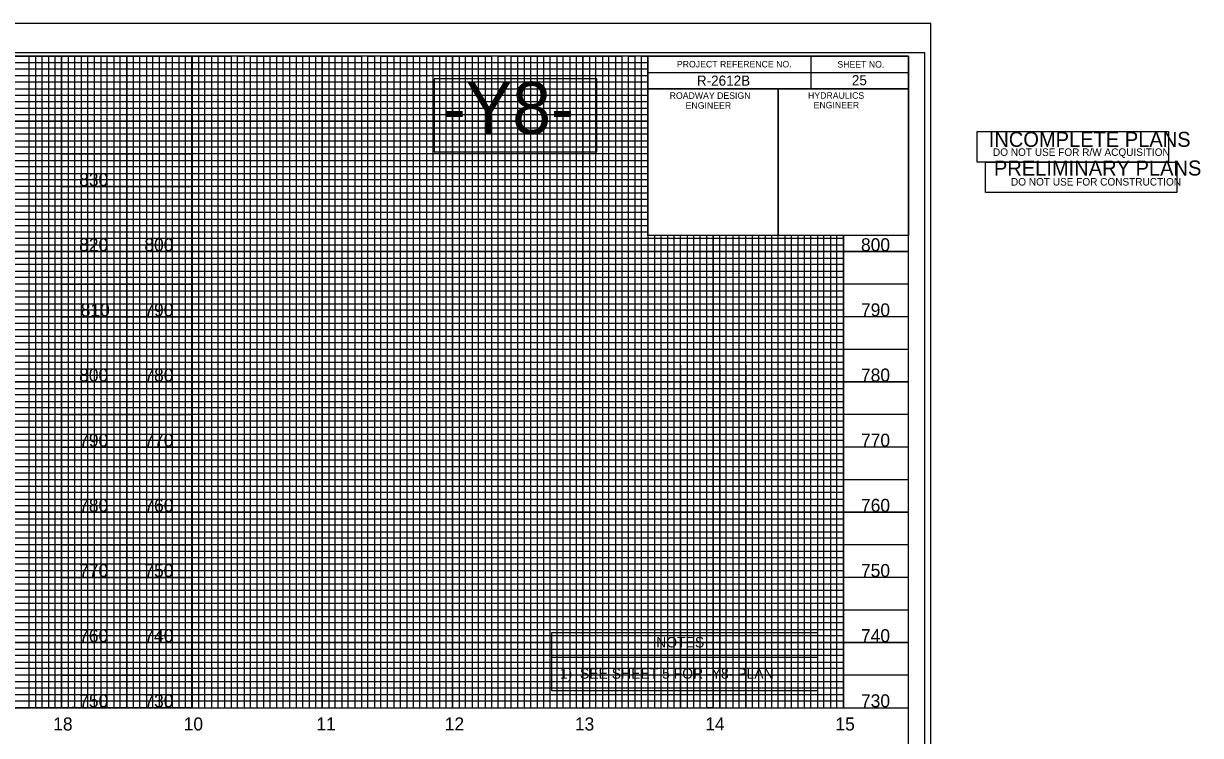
# Model space of a CAD drawing. Extents: x 600491 to 602382, y -54561 to -53461.
# Drawn here: x 601479 to 602382, y -54007 to -53461 of the extents above; entities that cross this region are included whole.
import ezdxf

# ---------------------------------------------------------------- set-up
doc = ezdxf.new("R2010")
doc.units = 0
for name, color, linetype in [('Default', 7, 'Continuous'), ('Exist Vertical Profile Horizontal Axis Label Major', 7, 'Continuous'), ('Exist Vertical Profile Vertical Axis Label', 7, 'Continuous'), ('Prop DSN Text', 7, 'Continuous'), ('Prop Grid Mask', 7, 'Continuous'), ('Prop VPI Label', 7, 'Continuous'), ('Sheet Cutting Line CELL', 7, 'Continuous'), ('Sheet Data Field CELL', 7, 'Continuous'), ('Sheet DOT Grid CELL', 7, 'Continuous'), ('Sheet Layout Profile Border Port 1', 7, 'Continuous'), ('Sheet Plot Border Inside CELL', 7, 'Continuous'), ('Sheet Plot Border Outside CELL', 7, 'Continuous'), ('Sheet Profile CELL', 7, 'Continuous'), ('Sheet Profile Grid Major CELL', 7, 'Continuous'), ('Sheet Profile Grid Middle CELL', 7, 'Continuous'), ('Sheet Profile Grid Minor CELL', 7, 'Continuous'), ('Sheet Sticker Incomplete CELL', 7, 'Continuous'), ('Sheet Sticker Preliminary CELL', 7, 'Continuous')]:
    doc.layers.add(name, color=color, linetype=linetype)

msp = doc.modelspace()

# ---------------------------------------------------------------- linework, layer by layer
at = {"layer": 'Default'}
for points in [[(600708.27, -53985.99), (601508.27, -53985.99), (601508.27, -53485.99), (600708.27, -53485.99)], [(601608.32, -53985.99), (602158.27, -53985.99), (602158.27, -53623.54), (601958.22, -53623.54), (601958.22, -53485.99), (601608.32, -53485.99)]]:
    msp.add_lwpolyline(points, close=True, dxfattribs=at)
at = {"layer": 'Prop Grid Mask'}
for p, q in [((601508.27, -53510.99), (601558.27, -53510.99)), ((601558.32, -53510.99), (601608.32, -53510.99)), ((601508.27, -53535.99), (601558.27, -53535.99)), ((601558.32, -53535.99), (601608.32, -53535.99)), ((601508.27, -53560.99), (601558.27, -53560.99)), ((601558.32, -53560.99), (601608.32, -53560.99)), ((601508.27, -53585.99), (601558.27, -53585.99)), ((601558.32, -53585.99), (601608.32, -53585.99)), ((601508.27, -53610.99), (601558.27, -53610.99)), ((601558.32, -53610.99), (601608.32, -53610.99)), ((601508.27, -53635.99), (601558.27, -53635.99)), ((601558.32, -53635.99), (601608.32, -53635.99)), ((601508.27, -53660.99), (601558.27, -53660.99)), ((601558.32, -53660.99), (601608.32, -53660.99)), ((601508.27, -53685.99), (601558.27, -53685.99)), ((601558.32, -53685.99), (601608.32, -53685.99)), ((601508.27, -53710.99), (601558.27, -53710.99)), ((601558.32, -53710.99), (601608.32, -53710.99)), ((601508.27, -53735.99), (601558.27, -53735.99)), ((601558.32, -53735.99), (601608.32, -53735.99)), ((601508.27, -53760.99), (601558.27, -53760.99)), ((601558.32, -53760.99), (601608.32, -53760.99)), ((601508.27, -53785.99), (601558.27, -53785.99)), ((601558.32, -53785.99), (601608.32, -53785.99)), ((601508.27, -53810.99), (601558.27, -53810.99)), ((601558.32, -53810.99), (601608.32, -53810.99)), ((601508.27, -53835.99), (601558.27, -53835.99)), ((601558.32, -53835.99), (601608.32, -53835.99)), ((601508.27, -53860.99), (601558.27, -53860.99)), ((601558.32, -53860.99), (601608.32, -53860.99)), ((601508.27, -53885.99), (601558.27, -53885.99)), ((601558.32, -53885.99), (601608.32, -53885.99)), ((601508.27, -53910.99), (601558.27, -53910.99)), ((601558.32, -53910.99), (601608.32, -53910.99)), ((601508.27, -53935.99), (601558.27, -53935.99)), ((601558.32, -53935.99), (601608.32, -53935.99)), ((601508.27, -53960.99), (601558.27, -53960.99)), ((601558.32, -53960.99), (601608.32, -53960.99))]:
    msp.add_line(p, q, dxfattribs=at)
for points in [[(601508.27, -53485.99), (601558.27, -53485.99), (601558.27, -53985.99), (601508.27, -53985.99)], [(601558.32, -53485.99), (601608.32, -53485.99), (601608.32, -53985.99), (601558.32, -53985.99)], [(601794.28, -53559.49), (601919.07, -53559.49), (601919.07, -53503.44), (601794.28, -53503.44)], [(601884.12, -53972.85), (602088.47, -53972.85), (602088.47, -53928.56), (601884.12, -53928.56)], [(601884.12, -53947.28), (602088.47, -53947.28), (602088.47, -53928.56), (601884.12, -53928.56)]]:
    msp.add_lwpolyline(points, close=True, dxfattribs=at)
at = {"layer": 'Sheet Cutting Line CELL'}
msp.add_line((602175.27, -53460.99), (600491.27, -53460.99), dxfattribs=at)
at = {"layer": 'Sheet DOT Grid CELL'}
for p, q in [((601508.27, -53985.99), (601508.27, -53485.99)), ((601558.27, -53985.99), (601558.27, -53485.99)), ((601608.27, -53985.99), (601608.27, -53485.99)), ((601658.27, -53985.99), (601658.27, -53485.99)), ((601708.27, -53985.99), (601708.27, -53485.99)), ((601758.27, -53985.99), (601758.27, -53485.99)), ((601808.27, -53985.99), (601808.27, -53485.99)), ((601858.27, -53985.99), (601858.27, -53485.99)), ((601908.27, -53985.99), (601908.27, -53485.99)), ((601958.22, -53535.99), (600658.27, -53535.99)), ((601958.22, -53585.99), (600658.27, -53585.99)), ((601958.27, -53985.99), (601958.27, -53623.54)), ((602008.27, -53985.99), (602008.27, -53623.54)), ((602058.27, -53985.99), (602058.27, -53623.54)), ((602108.27, -53985.99), (602108.27, -53623.54)), ((602158.27, -53635.99), (600658.27, -53635.99)), ((602158.27, -53685.99), (600658.27, -53685.99)), ((602158.27, -53735.99), (600658.27, -53735.99)), ((602158.27, -53785.99), (600658.27, -53785.99)), ((602158.27, -53835.99), (600658.27, -53835.99)), ((602158.27, -53885.99), (600658.27, -53885.99)), ((602158.27, -53935.99), (600658.27, -53935.99))]:
    msp.add_line(p, q, dxfattribs=at)
at = {"layer": 'Sheet Layout Profile Border Port 1'}
for points in [[(601508.27, -53985.99), (600708.27, -53985.99), (600708.27, -53485.99), (601508.27, -53485.99)], [(601608.27, -53485.99), (601608.27, -53985.99), (602108.27, -53985.99), (602108.27, -53623.54), (601958.22, -53623.54), (601958.22, -53485.99)]]:
    msp.add_lwpolyline(points, close=True, dxfattribs=at)
at = {"layer": 'Sheet Plot Border Inside CELL'}
msp.add_lwpolyline([(600504.27, -54538.54), (602170.77, -54538.54), (602170.77, -53483.44), (600504.27, -53483.44)], close=True, dxfattribs=at)
at = {"layer": 'Sheet Plot Border Outside CELL'}
msp.add_lwpolyline([(600491.27, -54560.99), (602175.27, -54560.99), (602175.27, -53460.99), (600491.27, -53460.99)], close=True, dxfattribs=at)
at = {"layer": 'Sheet Profile CELL'}
for p, q in [((602083.27, -53486.04), (602083.27, -53511.04)), ((601958.22, -53498.54), (602158.27, -53498.54)), ((602058.27, -53511.04), (602058.27, -53623.49)), ((600658.27, -53985.99), (602158.27, -53985.99))]:
    msp.add_line(p, q, dxfattribs=at)
for points in [[(602158.27, -53485.99), (600658.27, -53485.99), (600658.27, -54535.99), (602158.27, -54535.99)], [(601958.22, -53485.99), (602158.27, -53485.99), (602158.27, -53511.04), (601958.22, -53511.04)], [(601958.22, -53511.04), (602058.27, -53511.04), (602058.27, -53623.54), (601958.22, -53623.54)], [(602058.27, -53511.04), (602158.27, -53511.04), (602158.27, -53623.54), (602058.27, -53623.54)]]:
    msp.add_lwpolyline(points, close=True, dxfattribs=at)
at = {"layer": 'Sheet Profile Grid Major CELL'}
for points in [[(601458.27, -53485.99), (601508.27, -53485.99), (601508.27, -53985.99), (601558.27, -53985.99), (601558.27, -53485.99), (601608.27, -53485.99), (601608.27, -53985.99), (601658.27, -53985.99), (601658.27, -53485.99), (601708.27, -53485.99), (601708.27, -53985.99), (601758.27, -53985.99), (601758.27, -53485.99), (601808.27, -53485.99), (601808.27, -53985.99), (601858.27, -53985.99), (601858.27, -53485.99), (601908.27, -53485.99), (601908.27, -53985.99), (601958.27, -53985.99), (601958.27, -53485.99), (601984.57, -53485.99)], [(600658.27, -53535.99), (601958.27, -53535.99)], [(601958.27, -53585.99), (600658.27, -53585.99), (600658.27, -53635.99), (602158.27, -53635.99)], [(602008.27, -53623.54), (602008.27, -53985.99), (602058.27, -53985.99), (602058.27, -53985.99), (602058.27, -53623.54)], [(602108.27, -53623.54), (602108.27, -53985.99), (602158.27, -53985.99), (602158.27, -53635.99)], [(602158.27, -53685.99), (600658.27, -53685.99), (600658.27, -53735.99), (602158.27, -53735.99)], [(602158.27, -53785.99), (600658.27, -53785.99), (600658.27, -53835.99), (602158.27, -53835.99)], [(602158.27, -53885.99), (600658.27, -53885.99), (600658.27, -53885.99), (600658.27, -53935.99), (602158.27, -53935.99)]]:
    msp.add_lwpolyline(points, dxfattribs=at)
at = {"layer": 'Sheet Profile Grid Middle CELL'}
msp.add_line((600658.27, -53510.99), (601958.22, -53510.99), dxfattribs=at)
for points in [[(601433.27, -53985.99), (601483.27, -53985.99), (601483.27, -53485.99), (601533.27, -53485.99), (601533.27, -53985.99), (601583.27, -53985.99), (601583.27, -53485.99), (601633.27, -53485.99), (601633.27, -53985.99), (601683.27, -53985.99), (601683.27, -53485.99), (601733.27, -53485.99), (601733.27, -53985.99), (601783.27, -53985.99), (601783.27, -53485.99), (601833.27, -53485.99), (601833.27, -53985.99), (601883.27, -53985.99), (601883.27, -53485.99), (601933.27, -53485.99), (601933.27, -53985.99), (601983.27, -53985.99), (601983.27, -53623.54)], [(601958.27, -53560.99), (600658.27, -53560.99), (600658.27, -53610.99), (601958.27, -53610.99)], [(601983.27, -53723.19), (601983.27, -53985.99), (602033.27, -53985.99), (602033.27, -53623.54)], [(602033.27, -53723.19), (602033.27, -53985.99), (602083.27, -53985.99), (602083.27, -53623.54)], [(602158.27, -53660.99), (600658.27, -53660.99), (600658.27, -53710.99), (601983.27, -53710.99)], [(601983.27, -53710.99), (602158.27, -53710.99)], [(602158.27, -53760.99), (600658.27, -53760.99), (600658.27, -53810.99), (602158.27, -53810.99)], [(602158.27, -53860.99), (600658.27, -53860.99), (600658.27, -53910.99), (602158.27, -53910.99)], [(602158.27, -53960.99), (600658.27, -53960.99)]]:
    msp.add_lwpolyline(points, dxfattribs=at)
at = {"layer": 'Sheet Profile Grid Minor CELL'}
for p, q in [((600708.27, -53490.99), (601958.27, -53490.99)), ((601958.27, -53495.99), (600708.27, -53496.34)), ((600708.27, -53500.99), (601958.27, -53500.99)), ((601958.22, -53620.99), (600708.27, -53620.99)), ((602108.27, -53625.99), (600708.27, -53625.99)), ((602108.27, -53630.99), (600708.27, -53630.99)), ((600708.27, -53640.99), (602108.27, -53640.99)), ((602108.27, -53645.99), (600708.27, -53645.99)), ((600708.27, -53650.99), (602108.27, -53650.99)), ((602108.27, -53670.99), (600708.27, -53670.99)), ((600708.27, -53675.99), (602108.27, -53675.99)), ((602108.27, -53695.99), (600708.27, -53695.99)), ((600708.27, -53700.99), (602108.27, -53700.99)), ((602108.27, -53720.99), (600708.27, -53720.99)), ((600708.27, -53725.99), (602108.27, -53725.99)), ((602108.27, -53730.99), (600708.27, -53730.99)), ((600708.27, -53740.99), (602108.27, -53740.99)), ((602108.27, -53745.99), (600708.27, -53745.99)), ((600708.27, -53750.99), (602108.27, -53750.99)), ((602108.27, -53755.99), (600708.27, -53755.99)), ((600708.27, -53765.99), (602108.27, -53765.99)), ((602108.27, -53770.99), (600708.27, -53770.99)), ((600708.27, -53775.99), (602108.27, -53775.99)), ((602108.27, -53780.99), (600708.27, -53780.99)), ((600708.27, -53790.99), (602108.27, -53790.99)), ((602108.27, -53795.99), (600708.27, -53795.99)), ((600708.27, -53800.99), (602108.27, -53800.99)), ((602108.27, -53805.99), (600708.27, -53805.99)), ((600708.27, -53815.99), (602108.27, -53815.99)), ((602108.27, -53820.99), (600708.27, -53820.99)), ((600708.27, -53825.99), (602108.27, -53825.99)), ((602108.27, -53830.99), (600708.27, -53830.99)), ((600708.27, -53840.99), (602108.27, -53840.99)), ((602108.27, -53845.99), (600708.27, -53845.99)), ((600708.27, -53850.99), (602108.27, -53850.99)), ((602108.27, -53855.99), (600708.27, -53855.99)), ((600708.27, -53865.99), (602108.27, -53865.99)), ((602108.27, -53870.99), (600708.27, -53870.99)), ((602108.27, -53875.99), (600708.27, -53875.99)), ((602108.27, -53880.99), (600708.27, -53880.99)), ((600708.27, -53890.99), (602108.27, -53890.99)), ((602108.27, -53895.99), (600708.27, -53895.99)), ((600708.27, -53900.99), (602108.27, -53900.99)), ((602108.27, -53905.99), (600708.27, -53905.99)), ((600708.27, -53915.99), (602108.27, -53915.99)), ((602108.27, -53920.99), (600708.27, -53920.99)), ((600708.27, -53925.99), (602108.27, -53925.99)), ((602108.27, -53930.99), (600708.27, -53930.99)), ((600708.27, -53940.99), (602108.27, -53940.99)), ((602108.27, -53945.99), (600708.27, -53945.99)), ((600708.27, -53950.99), (602108.27, -53950.99)), ((602108.27, -53955.99), (600708.27, -53955.99)), ((600708.27, -53965.99), (602108.27, -53965.99)), ((602108.27, -53970.99), (600708.27, -53970.99)), ((600708.27, -53975.99), (602108.27, -53975.99))]:
    msp.add_line(p, q, dxfattribs=at)
for points in [[(601478.27, -53485.99), (601488.27, -53485.99), (601488.27, -53985.99), (601493.27, -53985.99), (601493.27, -53485.99), (601498.27, -53485.99), (601498.27, -53985.99), (601503.27, -53985.99), (601503.27, -53485.99), (601513.27, -53485.99), (601513.27, -53985.99), (601517.97, -53985.44), (601518.27, -53985.99), (601518.27, -53485.99), (601523.27, -53485.99), (601523.27, -53985.99), (601528.27, -53985.99), (601528.27, -53485.99), (601538.27, -53485.99), (601538.27, -53985.99), (601543.27, -53985.99)], [(601543.27, -53985.99), (601543.27, -53485.99), (601548.27, -53485.99), (601548.27, -53985.99), (601553.27, -53985.99), (601553.27, -53485.99), (601563.27, -53485.99), (601563.27, -53985.99), (601568.27, -53985.99), (601568.27, -53485.99), (601573.27, -53485.99), (601573.27, -53985.99), (601578.27, -53985.99), (601578.27, -53485.99), (601588.27, -53485.99), (601588.27, -53985.99), (601593.27, -53985.99), (601593.27, -53485.99), (601598.27, -53485.99), (601598.27, -53985.99), (601603.27, -53985.99), (601603.27, -53485.99), (601613.27, -53485.99), (601613.27, -53985.99), (601618.27, -53985.99), (601618.27, -53485.99), (601623.27, -53485.99), (601623.27, -53985.99), (601628.27, -53985.99), (601628.27, -53485.99), (601638.27, -53485.99), (601638.27, -53985.99), (601643.27, -53985.99), (601643.27, -53485.99), (601648.27, -53485.99), (601648.27, -53985.99), (601653.27, -53985.99), (601653.27, -53485.99), (601663.27, -53485.99), (601663.27, -53985.99), (601668.27, -53985.99), (601668.27, -53485.99), (601673.27, -53485.99), (601673.27, -53985.99), (601678.27, -53985.99), (601678.27, -53485.99), (601688.27, -53485.99), (601688.27, -53985.99), (601693.27, -53985.99), (601693.27, -53485.99), (601698.27, -53485.99), (601698.27, -53985.99), (601703.27, -53985.99), (601703.27, -53485.99), (601713.27, -53485.99), (601713.27, -53985.99), (601718.27, -53985.99), (601718.27, -53485.99), (601723.27, -53485.99), (601723.27, -53985.99), (601728.27, -53985.99), (601728.27, -53485.99), (601738.27, -53485.99), (601738.27, -53985.99), (601743.27, -53985.99), (601743.27, -53485.99), (601748.27, -53485.99), (601748.27, -53985.99), (601753.27, -53985.99), (601753.27, -53485.99), (601763.27, -53485.99), (601763.27, -53985.99), (601768.27, -53985.99), (601768.27, -53485.99), (601773.27, -53485.99), (601773.27, -53985.99), (601778.27, -53985.99), (601778.27, -53485.99), (601788.27, -53485.99), (601788.27, -53985.99), (601793.27, -53985.99), (601793.27, -53485.99), (601798.27, -53485.99), (601798.27, -53985.99), (601803.27, -53985.99), (601803.27, -53485.99), (601813.27, -53485.99), (601813.27, -53985.99), (601818.27, -53985.99), (601818.27, -53485.99), (601823.27, -53485.99), (601823.27, -53985.99), (601828.27, -53985.99), (601828.27, -53485.99), (601838.27, -53485.99), (601838.27, -53985.99), (601843.27, -53985.99), (601843.27, -53485.99), (601848.27, -53485.99), (601848.27, -53985.99)], [(601848.27, -53985.99), (601853.27, -53985.99), (601853.27, -53485.99), (601863.27, -53485.99), (601863.27, -53985.99), (601868.27, -53985.99), (601868.27, -53485.99), (601873.27, -53485.99), (601873.27, -53985.99), (601878.27, -53985.99), (601878.27, -53485.99), (601888.27, -53485.99), (601888.27, -53985.99), (601893.27, -53985.99), (601893.27, -53485.99), (601898.27, -53485.99), (601898.27, -53985.99), (601903.27, -53985.99), (601903.27, -53485.99), (601913.27, -53485.99), (601913.27, -53985.99), (601918.27, -53985.99), (601918.27, -53485.99), (601923.27, -53485.99), (601923.27, -53985.99), (601928.27, -53985.99), (601928.27, -53485.99), (601938.27, -53485.99), (601938.27, -53985.99), (601943.27, -53985.99), (601943.27, -53485.99), (601948.27, -53485.99), (601948.27, -53985.99), (601953.27, -53985.99), (601953.27, -53485.99), (601963.27, -53485.99)], [(601958.27, -53505.99), (600708.27, -53505.99), (600708.27, -53515.99), (601958.27, -53515.99)], [(601958.22, -53520.99), (600708.27, -53520.99), (600708.27, -53525.99), (601958.27, -53525.99)], [(601958.27, -53530.99), (600708.27, -53530.99), (600708.27, -53540.99), (601958.27, -53540.99)], [(601958.27, -53545.99), (600708.27, -53545.99), (600708.27, -53550.99), (601958.27, -53550.99)], [(601958.27, -53555.99), (600708.27, -53555.99), (600708.27, -53565.99), (601958.27, -53565.99)], [(601958.27, -53570.99), (600708.27, -53570.99), (600708.27, -53575.99), (601958.27, -53575.99)], [(601958.27, -53580.99), (600708.27, -53580.99), (600708.27, -53590.99), (601958.27, -53590.99)], [(601958.27, -53596.09), (600708.37, -53596.09), (600708.37, -53600.99), (601958.27, -53600.99)], [(601958.27, -53605.99), (600708.27, -53605.99), (600708.27, -53615.99), (601958.27, -53615.99)], [(601963.27, -53623.54), (601963.27, -53985.99), (601968.27, -53985.99), (601968.27, -53623.54)], [(601973.27, -53623.54), (601973.27, -53985.99), (601978.27, -53985.99), (601978.27, -53623.54)], [(601988.27, -53623.54), (601988.27, -53985.99), (601988.27, -53985.99), (601993.27, -53985.99), (601998.27, -53985.99), (601998.27, -53623.54)], [(601993.27, -53623.54), (601993.27, -53985.99)], [(602003.27, -53623.54), (602003.17, -53985.94), (602008.17, -53985.94), (602013.27, -53985.99), (602013.27, -53623.54)], [(602013.27, -53723.19), (602013.27, -53985.99), (602018.27, -53985.99), (602018.27, -53623.54)], [(602023.27, -53623.54), (602023.27, -53985.99), (602028.27, -53985.99), (602028.27, -53623.54)], [(602038.27, -53623.54), (602038.27, -53985.99), (602043.27, -53985.99), (602043.27, -53623.54)], [(602048.27, -53623.54), (602048.27, -53985.99), (602053.27, -53985.99), (602053.27, -53623.54)], [(602063.27, -53623.54), (602063.27, -53985.99), (602068.27, -53985.99), (602068.27, -53623.54)], [(602073.27, -53623.54), (602073.27, -53985.99), (602078.27, -53985.99), (602078.27, -53623.54)], [(602088.27, -53623.54), (602088.27, -53985.99), (602093.27, -53985.99), (602093.27, -53623.54)], [(602098.27, -53623.54), (602098.27, -53985.99), (602103.27, -53985.99), (602103.27, -53623.54)], [(602108.27, -53655.99), (600708.27, -53655.99), (600708.27, -53665.99), (602108.27, -53665.99)], [(602108.27, -53680.99), (600708.27, -53680.99), (600708.27, -53690.99), (602108.27, -53690.99)], [(602108.27, -53705.99), (600708.27, -53705.99), (600708.27, -53715.99), (602108.27, -53715.99)], [(602108.27, -53980.99), (600708.27, -53980.99)]]:
    msp.add_lwpolyline(points, dxfattribs=at)
at = {"layer": 'Sheet Sticker Incomplete CELL'}
msp.add_lwpolyline([(602210.8, -53567.32), (602210.8, -53543.82), (602357.8, -53543.82), (602357.8, -53567.32)], close=True, dxfattribs=at)
at = {"layer": 'Sheet Sticker Preliminary CELL'}
msp.add_lwpolyline([(602217.21, -53590.77), (602217.21, -53567.27), (602364.21, -53567.27), (602364.21, -53590.77)], close=True, dxfattribs=at)

# ---------------------------------------------------------------- texts
at = {"layer": 'Exist Vertical Profile Horizontal Axis Label Major'}
for s, p in [('18', (601501.8, -54003.49)), ('10', (601601.91, -54003.49)), ('11', (601703.75, -54003.49)), ('12', (601802.29, -54003.49)), ('13', (601902.13, -54003.49)), ('14', (602002.19, -54003.49)), ('15', (602102.11, -54003.49))]:
    msp.add_text(s, height=10, dxfattribs=at).set_placement(p)
at = {"layer": 'Exist Vertical Profile Vertical Axis Label'}
for s, p in [('830', (601521.7, -53585.74)), ('820', (601521.7, -53635.74)), ('800', (601571.75, -53635.74)), ('800', (602121.7, -53635.74)), ('810', (601522.9, -53685.74)), ('790', (601571.75, -53685.74)), ('790', (602121.7, -53685.74)), ('800', (601521.7, -53735.74)), ('780', (601571.75, -53735.74)), ('780', (602121.7, -53735.74)), ('790', (601521.7, -53785.74)), ('770', (601571.75, -53785.74)), ('770', (602121.7, -53785.74)), ('780', (601521.7, -53835.74)), ('760', (601571.75, -53835.74)), ('760', (602121.7, -53835.74)), ('770', (601521.7, -53885.74)), ('750', (601571.75, -53885.74)), ('750', (602121.7, -53885.74)), ('760', (601521.7, -53935.74)), ('740', (601571.75, -53935.74)), ('740', (602121.7, -53935.74)), ('750', (601521.7, -53985.74)), ('730', (601571.75, -53985.74)), ('730', (602121.7, -53985.74))]:
    msp.add_text(s, height=10, dxfattribs=at).set_placement(p)
at = {"layer": 'Prop DSN Text'}
for s, p in [('NOTES', (601964.55, -53939.75)), ('1)  SEE SHEET 5 FOR -Y8- PLAN', (601890.6, -53963.76))]:
    msp.add_text(s, height=8, dxfattribs=at).set_placement(p)
at = {"layer": 'Prop VPI Label'}
msp.add_text('-Y8-', height=40, dxfattribs=at).set_placement((601800.57, -53545.76))
at = {"layer": 'Sheet Data Field CELL'}
for s, p in [('R-2612B  ', (601995.76, -53508.68)), ('25', (602114.71, -53508.38))]:
    msp.add_text(s, height=7.75, dxfattribs=at).set_placement(p)
at = {"layer": 'Sheet Profile CELL'}
for s, height, p in [('PROJECT REFERENCE NO.', 5.0001, (601980.44, -53494.68)), ('SHEET NO.', 5, (602103.59, -53494.78)), ('ROADWAY DESIGN', 5.0001, (601974.89, -53518.78)), ('HYDRAULICS', 5, (602081.09, -53518.73)), ('ENGINEER', 5, (601987.14, -53526.38)), ('ENGINEER', 5, (602085.34, -53526.08))]:
    msp.add_text(s, height=height, dxfattribs=at).set_placement(p)
at = {"layer": 'Sheet Sticker Incomplete CELL'}
for s, height, p in [('INCOMPLETE PLANS', 11.52, (602219.75, -53555.62)), ('DO NOT USE FOR R/W ACQUISITION', 5.76, (602223, -53562.57))]:
    msp.add_text(s, height=height, dxfattribs=at).set_placement(p)
at = {"layer": 'Sheet Sticker Preliminary CELL'}
for s, height, p in [('PRELIMINARY PLANS', 11.52, (602223.71, -53577.62)), ('DO NOT USE FOR CONSTRUCTION', 5.76, (602236.81, -53585.32))]:
    msp.add_text(s, height=height, dxfattribs=at).set_placement(p)

doc.saveas('drawing.dxf')
